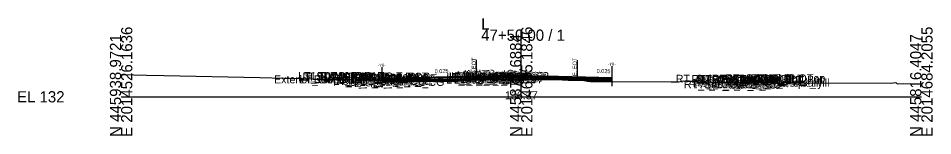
# Model space of a CAD drawing. Extents: x -26 to 4203, y -10 to 9526.
# Drawn here: x 2974.3 to 3202.8, y 7490.3 to 7519.6 of the extents above; entities that cross this region are included whole.
import ezdxf

# ---------------------------------------------------------------- set-up
doc = ezdxf.new("R2010")
doc.units = 0
for name, color, linetype in [('Default', 7, 'Continuous'), ('Exist CMT Pavement', 7, 'Continuous'), ('Exist Cross Section Cell', 7, 'Continuous'), ('Exist XS Center Line Elevation Label', 7, 'Continuous'), ('Exist XS Ground Line', 7, 'Continuous'), ('Prop CMT Concrete Structures', 7, 'Continuous'), ('Prop CMT Pvmt Course 1', 7, 'Continuous'), ('Prop CMT Pvmt Course 1 CG', 7, 'Continuous'), ('Prop CMT Pvmt Course 1 Wedge', 7, 'Continuous'), ('Prop CMT Pvmt Course 2', 7, 'Continuous'), ('Prop CMT Pvmt Course 2 Wedge', 7, 'Continuous'), ('Prop CMT Pvmt Course 3', 7, 'Continuous'), ('Prop CMT Pvmt Course 3 Wedge', 7, 'Continuous'), ('Prop CMT Pvmt Surface', 7, 'Continuous'), ('Prop CMT Pvmt Wedge Surface 1', 7, 'Continuous'), ('Prop CMT Pvmt Wedge Surface 2', 7, 'Continuous'), ('Prop CMT Pvmt Wedge Surface 3', 7, 'Continuous'), ('Prop CMT Shear Line', 7, 'Continuous'), ('Prop CMT Shear Line Text', 7, 'Continuous'), ('Prop CMT Subgrade Earthwork', 7, 'Continuous'), ('Prop XS Label Text', 7, 'Continuous'), ('Prop XS SE Text', 7, 'Continuous'), ('Scratch_Level_0', 7, 'Continuous')]:
    doc.layers.add(name, color=color, linetype=linetype)

msp = doc.modelspace()

# ---------------------------------------------------------------- linework, layer by layer
at = {"layer": 'Exist CMT Pavement'}
for p, q in [((3088.74, 7504.21), (3090.69, 7504.26)), ((3090.69, 7504.26), (3092.83, 7504.31)), ((3092.83, 7504.31), (3096.1, 7504.36)), ((3096.1, 7504.36), (3099.2, 7504.38)), ((3099.2, 7504.38), (3105.42, 7504.32)), ((3105.42, 7504.32), (3110.28, 7504.25)), ((3112.49, 7504.14), (3113.96, 7504.17))]:
    msp.add_line(p, q, dxfattribs=at)
msp.add_lwpolyline([(3110.28, 7504.25), (3111.75, 7504.17), (3112.49, 7504.14)], dxfattribs=at)
at = {"layer": 'Exist Cross Section Cell'}
for p, q in [((3100, 7500), (3100, 7516.76)), ((3000, 7500), (3100, 7500)), ((3100, 7500), (3200, 7500))]:
    msp.add_line(p, q, dxfattribs=at)
at = {"layer": 'Exist XS Ground Line'}
msp.add_lwpolyline([(3000, 7505.58), (3006.33, 7505.43), (3010.8, 7505.33), (3034.66, 7504.77), (3040.79, 7504.63), (3045.33, 7504.54), (3048.12, 7504.45), (3070.74, 7504.01), (3078.37, 7503.78), (3078.67, 7503.79), (3079.31, 7503.81), (3080.52, 7503.83), (3083.43, 7503.86), (3085.38, 7504.01), (3086.53, 7504.09), (3087.57, 7504.15), (3088.23, 7504.19), (3088.74, 7504.21), (3089.65, 7504.23), (3090.69, 7504.26), (3092.03, 7504.29), (3092.48, 7504.3), (3092.83, 7504.31), (3096.1, 7504.36), (3099.2, 7504.38), (3099.62, 7504.38), (3100.18, 7504.37), (3101.41, 7504.36), (3102.34, 7504.34), (3103.18, 7504.33), (3104.3, 7504.33), (3104.95, 7504.33), (3105.42, 7504.32), (3108.3, 7504.28), (3108.67, 7504.27), (3110.28, 7504.25), (3111.75, 7504.17), (3112.49, 7504.14), (3113.96, 7504.17), (3115.62, 7504.03), (3116.58, 7503.93), (3117.33, 7503.84), (3117.81, 7503.82), (3118.33, 7503.83), (3137.5, 7503.76), (3139.28, 7503.72), (3140.62, 7503.97), (3141.4, 7503.93), (3143.7, 7503.92), (3144.13, 7503.48), (3144.8, 7503.51), (3145.75, 7503.58), (3159.77, 7503.44), (3163.78, 7503.39), (3164.91, 7503.34), (3165.42, 7503.32), (3165.82, 7503.78), (3166.54, 7503.51), (3170.92, 7503.51), (3192.29, 7503.42), (3193.59, 7503.52), (3193.92, 7503.26), (3195.58, 7503.29), (3200, 7503.15)], dxfattribs=at)
at = {"layer": 'Prop CMT Concrete Structures'}
for points in [[(3096, 7505.49), (3095.99, 7505.66), (3095.24, 7505.91), (3094, 7505.94), (3092.76, 7505.61), (3092.01, 7505.36), (3092, 7505.19)], [(3092, 7505.19), (3096, 7505.49)]]:
    msp.add_lwpolyline(points, dxfattribs=at)
at = {"layer": 'Prop CMT Pvmt Course 1'}
for points in [[(3092, 7505.19), (3065.25, 7504.53)], [(3088.74, 7504.99), (3092, 7505.07)], [(3092, 7505.19), (3096, 7505.49)], [(3096, 7505.24), (3092, 7504.94)], [(3092, 7504.94), (3092, 7505.19)], [(3092, 7504.94), (3092, 7505.19)], [(3092, 7505.07), (3092, 7504.94), (3092, 7504.94)], [(3096, 7505.49), (3096, 7505.24)], [(3096, 7505.49), (3122.75, 7504.83)], [(3096, 7505.24), (3096, 7505.49)], [(3113.96, 7504.92), (3096, 7505.37)], [(3096, 7505.37), (3096, 7505.24), (3096, 7505.24)], [(3065.25, 7504.28), (3076.88, 7504.57)], [(3065.25, 7504.53), (3065.25, 7504.28)], [(3088.74, 7504.86), (3088.74, 7504.99)], [(3113.96, 7504.8), (3113.96, 7504.92)], [(3122.75, 7504.58), (3117.33, 7504.71)]]:
    msp.add_lwpolyline(points, dxfattribs=at)
at = {"layer": 'Prop CMT Pvmt Course 1 CG'}
msp.add_lwpolyline([(3065.25, 7503.61), (3065.25, 7503.94)], dxfattribs=at)
at = {"layer": 'Prop CMT Pvmt Course 1 Wedge'}
for points in [[(3088.74, 7504.99), (3089.65, 7505.01), (3090.69, 7505.04), (3092, 7505.07)], [(3092, 7505.07), (3092, 7504.94)], [(3096, 7505.24), (3096, 7505.37)], [(3096, 7505.37), (3096.04, 7505.37), (3096.1, 7505.37), (3099.2, 7505.29), (3099.62, 7505.28), (3100.18, 7505.26), (3101.41, 7505.23), (3102.34, 7505.21), (3103.18, 7505.19), (3104.3, 7505.16), (3104.95, 7505.15), (3105.42, 7505.13), (3108.3, 7505.06), (3108.67, 7505.05), (3110.28, 7505.01), (3111.75, 7504.98), (3112.49, 7504.96), (3113.86, 7504.92), (3113.95, 7504.92), (3113.96, 7504.92), (3113.96, 7504.92)], [(3113.96, 7504.8), (3113.96, 7504.8), (3113.95, 7504.8), (3113.86, 7504.8), (3112.49, 7504.83), (3111.75, 7504.85), (3110.28, 7504.89), (3108.67, 7504.93), (3108.3, 7504.94), (3105.42, 7505.01), (3104.95, 7505.02), (3104.3, 7505.04), (3103.18, 7505.06), (3102.34, 7505.09), (3101.41, 7505.11), (3100.18, 7505.14), (3099.62, 7505.15), (3099.2, 7505.16), (3096.1, 7505.24), (3096.04, 7505.24), (3096, 7505.24)], [(3088.74, 7504.86), (3088.74, 7504.99)], [(3092, 7504.94), (3090.69, 7504.91), (3089.65, 7504.89), (3088.74, 7504.86)], [(3113.96, 7504.92), (3113.96, 7504.8), (3113.96, 7504.8)]]:
    msp.add_lwpolyline(points, dxfattribs=at)
at = {"layer": 'Prop CMT Pvmt Course 2'}
for points in [[(3092, 7504.94), (3096, 7505.24)], [(3096, 7505.24), (3096, 7504.91)], [(3088.74, 7504.86), (3065.25, 7504.28)], [(3065.25, 7503.94), (3088.74, 7504.53)], [(3065.25, 7504.28), (3065.25, 7503.94)], [(3088.74, 7504.53), (3088.74, 7504.86)], [(3092, 7504.61), (3092, 7504.94)], [(3096, 7504.91), (3092, 7504.61)], [(3113.96, 7504.46), (3113.96, 7504.8)], [(3113.96, 7504.8), (3122.75, 7504.58)], [(3122.75, 7504.24), (3113.96, 7504.46)]]:
    msp.add_lwpolyline(points, dxfattribs=at)
at = {"layer": 'Prop CMT Pvmt Course 2 Wedge'}
for points in [[(3096, 7504.91), (3096, 7505.24)], [(3096, 7505.24), (3096.04, 7505.24), (3096.1, 7505.24), (3099.2, 7505.16), (3099.62, 7505.15), (3100.18, 7505.14), (3101.41, 7505.11), (3102.34, 7505.09), (3103.18, 7505.06), (3104.3, 7505.04), (3104.95, 7505.02), (3105.42, 7505.01), (3108.3, 7504.94), (3108.67, 7504.93), (3110.28, 7504.89), (3111.75, 7504.85), (3112.49, 7504.83), (3113.86, 7504.8), (3113.95, 7504.8), (3113.96, 7504.8), (3113.96, 7504.8)], [(3088.74, 7504.86), (3089.65, 7504.89), (3090.69, 7504.91), (3092, 7504.94)], [(3088.74, 7504.53), (3088.74, 7504.86)], [(3092, 7504.61), (3090.69, 7504.58), (3089.65, 7504.55), (3088.74, 7504.53)], [(3092, 7504.94), (3092, 7504.61)], [(3113.96, 7504.46), (3113.96, 7504.46), (3113.95, 7504.46), (3113.86, 7504.46), (3112.49, 7504.5), (3111.75, 7504.52), (3110.28, 7504.55), (3108.67, 7504.59), (3108.3, 7504.6), (3105.42, 7504.68), (3104.95, 7504.69), (3104.3, 7504.7), (3103.18, 7504.73), (3102.34, 7504.75), (3101.41, 7504.78), (3100.18, 7504.81), (3099.62, 7504.82), (3099.2, 7504.83), (3096.1, 7504.91), (3096.04, 7504.91), (3096, 7504.91)], [(3113.96, 7504.8), (3113.96, 7504.46), (3113.96, 7504.46)]]:
    msp.add_lwpolyline(points, dxfattribs=at)
at = {"layer": 'Prop CMT Pvmt Course 3'}
for points in [[(3088.74, 7504.53), (3065.25, 7503.94)], [(3065.25, 7503.61), (3088.74, 7504.2)], [(3065.25, 7503.94), (3065.25, 7503.61)], [(3092, 7504.61), (3096, 7504.91)], [(3113.96, 7504.46), (3122.75, 7504.24)], [(3113.96, 7504.13), (3113.96, 7504.46)], [(3122.75, 7503.91), (3113.96, 7504.13)]]:
    msp.add_lwpolyline(points, dxfattribs=at)
at = {"layer": 'Prop CMT Pvmt Course 3 Wedge'}
for points in [[(3092, 7504.29), (3090.69, 7504.26), (3089.65, 7504.23), (3088.74, 7504.21), (3088.23, 7504.19), (3087.57, 7504.15), (3086.53, 7504.09), (3085.38, 7504.01), (3083.68, 7503.88), (3083.43, 7503.86), (3080.52, 7503.83), (3079.31, 7503.81), (3079.3, 7503.81), (3078.67, 7503.79), (3078.37, 7503.78), (3076.88, 7503.82)], [(3088.74, 7504.53), (3089.65, 7504.55), (3090.69, 7504.58), (3092, 7504.61)], [(3096, 7504.91), (3096.04, 7504.91), (3096.1, 7504.91), (3099.2, 7504.83), (3099.62, 7504.82), (3100.18, 7504.81), (3101.41, 7504.78), (3102.34, 7504.75), (3103.18, 7504.73), (3104.3, 7504.7), (3104.95, 7504.69), (3105.42, 7504.68), (3108.3, 7504.6), (3108.67, 7504.59), (3110.28, 7504.55), (3111.75, 7504.52), (3112.49, 7504.5), (3113.86, 7504.46), (3113.95, 7504.46), (3113.96, 7504.46), (3113.96, 7504.46)], [(3117.33, 7503.84), (3116.58, 7503.93), (3116.31, 7503.99), (3115.62, 7504.03), (3115.38, 7504.1), (3114.09, 7504.16), (3113.96, 7504.17), (3113.95, 7504.12), (3113.86, 7504.11), (3112.49, 7504.14), (3111.75, 7504.17), (3110.28, 7504.25), (3108.67, 7504.27), (3108.3, 7504.28), (3105.42, 7504.32), (3104.95, 7504.33), (3104.3, 7504.33), (3103.18, 7504.33), (3102.34, 7504.34), (3101.41, 7504.36), (3100.18, 7504.37), (3099.62, 7504.38), (3099.2, 7504.38), (3096.1, 7504.36), (3096.04, 7504.36), (3096, 7504.36)]]:
    msp.add_lwpolyline(points, dxfattribs=at)
at = {"layer": 'Prop CMT Pvmt Surface'}
for points in [[(3092, 7505.19), (3065.25, 7504.53)], [(3092, 7505.19), (3096, 7505.49)], [(3096, 7505.49), (3122.75, 7504.83)]]:
    msp.add_lwpolyline(points, dxfattribs=at)
at = {"layer": 'Prop CMT Pvmt Wedge Surface 1'}
for points in [[(3092, 7505.07), (3088.74, 7504.99)], [(3092, 7505.19), (3092, 7504.94), (3092, 7504.94), (3092, 7505.07)], [(3096, 7505.49), (3096, 7505.24), (3096, 7505.24), (3096, 7505.37)], [(3096, 7505.37), (3113.96, 7504.92)], [(3088.74, 7504.86), (3065.25, 7504.28)], [(3065.25, 7504.28), (3065.25, 7504.53)], [(3088.74, 7504.99), (3088.74, 7504.86)], [(3113.96, 7504.92), (3113.96, 7504.8)], [(3113.96, 7504.8), (3122.75, 7504.58)]]:
    msp.add_lwpolyline(points, dxfattribs=at)
at = {"layer": 'Prop CMT Pvmt Wedge Surface 2'}
for points in [[(3092, 7505.19), (3092, 7504.94)], [(3096, 7505.49), (3096, 7505.24)], [(3096, 7505.24), (3113.96, 7504.8)], [(3065.25, 7504.28), (3065.25, 7504.53)], [(3092, 7504.94), (3088.74, 7504.86)]]:
    msp.add_lwpolyline(points, dxfattribs=at)
at = {"layer": 'Prop CMT Pvmt Wedge Surface 3'}
for points in [[(3092, 7505.19), (3092, 7504.61)], [(3096, 7505.49), (3096, 7504.91)], [(3065.25, 7503.94), (3065.25, 7504.53)], [(3092, 7504.61), (3088.74, 7504.53)], [(3096, 7504.91), (3113.96, 7504.46)]]:
    msp.add_lwpolyline(points, dxfattribs=at)
at = {"layer": 'Prop CMT Shear Line'}
for p, q in [((3065.25, 7502.35), (3065.25, 7507.36)), ((3122.75, 7502.65), (3122.75, 7507.66))]:
    msp.add_line(p, q, dxfattribs=at)
at = {"layer": 'Prop CMT Subgrade Earthwork'}
for p, q in [((3065.25, 7503.61), (3065.25, 7504.53)), ((3122.75, 7503.91), (3122.75, 7504.83)), ((3122.75, 7503.91), (3122.75, 7503.82))]:
    msp.add_line(p, q, dxfattribs=at)
for points in [[(3088.74, 7504.2), (3065.25, 7503.61)], [(3088.74, 7504.2), (3088.74, 7504.21)], [(3113.96, 7504.13), (3113.96, 7504.17)], [(3113.96, 7504.13), (3122.75, 7503.91)]]:
    msp.add_lwpolyline(points, dxfattribs=at)
at = {"layer": 'Prop XS Label Text'}
for p, q in [((3088.74, 7509.21), (3088.74, 7504.21)), ((3113.96, 7509.17), (3113.96, 7504.17))]:
    msp.add_line(p, q, dxfattribs=at)

# ---------------------------------------------------------------- texts
at = {"layer": 'Default'}
msp.add_text('-', height=0.0001, dxfattribs=at).set_placement((3000, 7500))
msp.add_text('-', height=0.0001, dxfattribs=at).set_placement((3000, 7500))
at = {"layer": 'Exist Cross Section Cell'}
for s, p in [('L', (3090, 7516.76)), ('47+50.00 / 1', (3090, 7513.96)), ('EL 132', (2974, 7498.6))]:
    msp.add_text(s, height=2.8, dxfattribs=at).set_placement(p)
for s, p in [('E 2014526.1636', (3002.8, 7490)), ('E 2014605.1846', (3102.8, 7490)), ('E 2014684.2055', (3202.8, 7490)), ('N 445938.9721', (3000, 7490)), ('N 445877.6884', (3100, 7490)), ('N 445816.4047', (3200, 7490))]:
    msp.add_text(s, height=2.8, rotation=90, dxfattribs=at).set_placement(p)
at = {"layer": 'Exist XS Center Line Elevation Label'}
msp.add_text('136.37', height=2, dxfattribs=at).set_placement((3095.94, 7499.37))
at = {"layer": 'Prop CMT Shear Line Text'}
for p in [(3064.16, 7507.48), (3121.66, 7507.78)]:
    msp.add_text('-Y8-', height=0.75, dxfattribs=at).set_placement(p)
at = {"layer": 'Prop XS Label Text'}
for p in [(3088.64, 7505.23), (3113.86, 7505.19)]:
    msp.add_text('E. EOT', height=1, rotation=90, dxfattribs=at).set_placement(p)
at = {"layer": 'Prop XS SE Text'}
for rotation, p in [(1.4303, (3078.37, 7505.85)), (358.568, (3118.83, 7505.95))]:
    msp.add_text('0.025', height=1, rotation=rotation, dxfattribs=at).set_placement(p)
at = {"layer": 'Scratch_Level_0'}
for s, p in [('Exterior Boundary', (3038.21, 7503.34)), ('LT_SDWK_Out_Top', (3044.22, 7504.19)), ('LT_SDWK_Out_Bot', (3044.26, 7503.86)), ('LT_Slope_Fill', (3044.59, 7503.34)), ('LT_Sub_Trench_Out_DLT', (3045.3, 7504.05)), ('LT_CSLP_Pnt', (3047.66, 7504.19)), ('LT_SDWK_In_Top', (3050.85, 7504.09)), ('LT_SDWK_In_Bot', (3050.88, 7503.76)), ('LT_CG1_Shelf_Out', (3053.04, 7502.97)), ('LT_CG_Top_Face', (3054.75, 7504)), ('LT_CG_Top_BOC', (3055.27, 7504)), ('LT_CG_Bot_BOC', (3055.3, 7502.99)), ('LT_CG_Top_Gut', (3055.73, 7503.5)), ('LT_CG_Bot_IE', (3059.4, 7503.05)), ('LT_PV2_OEOT', (3059.66, 7503.38)), ('LT_PV3_OEOT', (3059.66, 7503.05)), ('LT_PV1_OEOT', (3060.23, 7503.63)), ('LT_Sub_OEEOP', (3081.21, 7503.28)), ('LT_Sub_OEEOP', (3081.21, 7503.28)), ('LT_PV2_OEEOP', (3081.31, 7503.94)), ('LT_PV2_OEEOP', (3081.31, 7503.94)), ('LT_PV3_OEEOP', (3081.31, 7503.61)), ('LT_PV3_OEEOP', (3081.31, 7503.61)), ('LT_PV1_OEEOP', (3081.87, 7504.07)), ('LT_PV1_OEEOP', (3081.87, 7504.07)), ('LT_PV2_IEEOP', (3081.95, 7503.94)), ('LT_PV1_IEEOP', (3082.52, 7504.07)), ('LT_PV2_PGL1', (3082.88, 7503.94)), ('LT_PV3_PGL1', (3082.88, 7503.61)), ('LT_PV2_PGL', (3083.21, 7503.94)), ('LT_PV4_PGL', (3083.21, 7503.28)), ('LT_PV1_PGL', (3083.78, 7504.19)), ('MI_Face In', (3083.9, 7504.36)), ('RT_Sub_OEEOP', (3085.17, 7503.38)), ('RT_PV2_OEEOP', (3085.26, 7504.04)), ('RT_PV3_OEEOP', (3085.26, 7503.71)), ('MI_Top In', (3085.61, 7504.61)), ('RT_PV1_OEEOP', (3085.83, 7504.17)), ('RT_PV2_IEEOP', (3085.91, 7504.04)), ('MI_Face Out', (3086.26, 7504.46)), ('MI_Top Out', (3086.47, 7504.71)), ('RT_PV1_IEEOP', (3086.47, 7504.17)), ('RT_PV2_PGL1', (3086.83, 7504.24)), ('RT_PV3_PGL1', (3086.83, 7503.91)), ('MI_Crown', (3087.07, 7504.74)), ('RT_PV2_PGL', (3087.17, 7504.04)), ('RT_PV4_PGL', (3087.17, 7503.58)), ('MI_Bot Out', (3087.26, 7504.29)), ('RT_PV1_PGL', (3087.73, 7504.29)), ('RT_Sub_Trench_Out_DLT', (3138.62, 7503.48)), ('RT_CG_Top_Face', (3142.55, 7503.43)), ('RT_PV1_OEOT', (3144.03, 7503.06)), ('RT_CG_Top_BOC', (3144.08, 7503.43)), ('RT_SDWK_In_Top', (3147.65, 7503.52)), ('RT_SDWK_In_Bot', (3147.68, 7503.19)), ('RT_SDWK_Out_Top', (3151.03, 7503.62)), ('RT_SDWK_Out_Bot', (3151.06, 7503.29)), ('RT_Shld_O', (3157.38, 7503.61)), ('CSLP_Pnt', (3158.21, 7503.62)), ('LT_Sub_OEOP', (3056.26, 7502.63)), ('LT_Sub_OEOT_CG', (3056.86, 7502.72)), ('LT_Sub_OEOT', (3059.57, 7502.72)), ('RT_Sub_OEOT_CG', (3140.66, 7502.14)), ('RT_CG1_Shelf_Out', (3142.84, 7502.4)), ('RT_CG_Bot_IE', (3143.21, 7502.48)), ('RT_Sub_OEOT', (3143.37, 7502.14)), ('RT_PV2_OEOT', (3143.47, 7502.81)), ('RT_PV3_OEOT', (3143.47, 7502.48)), ('RT_CG_Top_Gut', (3143.53, 7502.93)), ('RT_CG_Bot_BOC', (3144.11, 7502.41)), ('RT_Sub_OEOP', (3146.74, 7502.06)), ('Exterior Boundary', (3153.92, 7502.51)), ('RT_Slope_Fill', (3160.25, 7502.51))]:
    msp.add_text(s, height=2, dxfattribs=at).set_placement(p)

doc.saveas('drawing.dxf')
